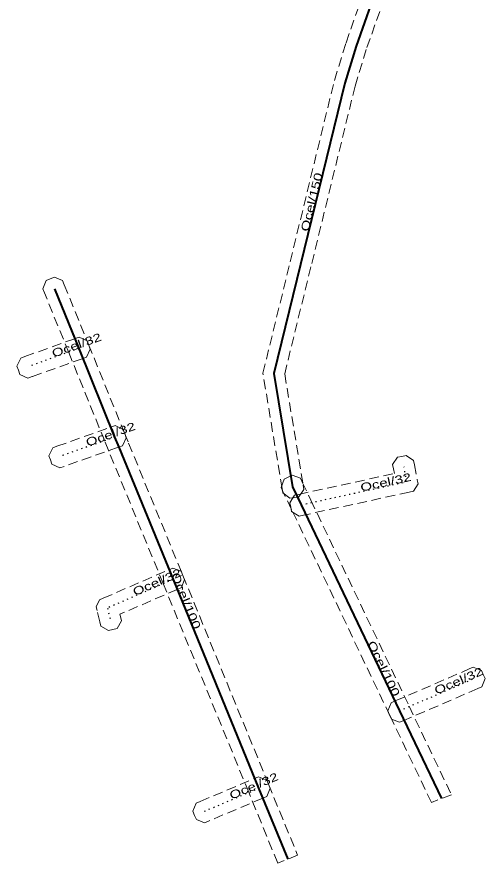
# Model space of a CAD drawing. Extents: x -583333 to -583115, y -1209681 to -1209498.
# Drawn here: x -583253.7 to -583209.9, y -1209656.4 to -1209577.1 of the extents above; entities that cross this region are included whole.
import ezdxf

# ---------------------------------------------------------------- set-up
doc = ezdxf.new("R2010")
doc.units = 0
doc.header["$LTSCALE"] = 0.3
doc.linetypes.add('DOTTED', pattern=[1.5, 0.3, -1.2])
doc.linetypes.add('MEDIUM_DASHED', pattern=[4.5, 3, -1.5])
for name, color, linetype, lineweight in [('1', 7, 'MEDIUM_DASHED', 13), ('14', 7, 'Continuous', 40), ('18', 7, 'DOTTED', 25)]:
    doc.layers.add(name, color=color, linetype=linetype, lineweight=lineweight)
doc.layers.add('20', color=7, linetype='Continuous')

msp = doc.modelspace()

# ---------------------------------------------------------------- linework, layer by layer
at = {"layer": '1'}
for points in [[(-583218.709, -1209573.68), (-583218.846, -1209574.071), (-583220.99, -1209580.183), (-583222.045, -1209583.616), (-583226.179, -1209600.567), (-583228.63, -1209610.589), (-583226.903, -1209621.007), (-583226.835, -1209621.415), (-583227.318, -1209622.089), (-583227.727, -1209622.157), (-583228.135, -1209622.225), (-583228.809, -1209621.742), (-583228.877, -1209621.333), (-583230.67, -1209610.511), (-583228.121, -1209600.093), (-583223.975, -1209583.084), (-583222.89, -1209579.557), (-583220.734, -1209573.409), (-583220.597, -1209573.018), (-583219.85, -1209572.659), (-583219.459, -1209572.796), (-583219.068, -1209572.933)], [(-583227.42, -1209655.685), (-583229.281, -1209656.419), (-583231.995, -1209649.789), (-583240.005, -1209630.239), (-583245.096, -1209617.819), (-583245.476, -1209616.887), (-583248.837, -1209608.596), (-583251.116, -1209602.987), (-583251.272, -1209602.603), (-583250.951, -1209601.84), (-583250.567, -1209601.684), (-583250.183, -1209601.528), (-583249.42, -1209601.849), (-583249.264, -1209602.233), (-583246.983, -1209607.844), (-583243.624, -1209616.133), (-583243.244, -1209617.061), (-583238.155, -1209629.481), (-583230.145, -1209649.031)], [(-583247.183, -1209609.022), (-583247.573, -1209609.162), (-583252.273, -1209610.842), (-583252.663, -1209610.981), (-583253.412, -1209610.627), (-583253.552, -1209610.237), (-583253.691, -1209609.847), (-583253.337, -1209609.098), (-583252.947, -1209608.958), (-583248.247, -1209607.278), (-583247.857, -1209607.139), (-583247.108, -1209607.493), (-583246.968, -1209607.883), (-583246.829, -1209608.273)], [(-583243.825, -1209617.313), (-583244.215, -1209617.452), (-583249.275, -1209619.252), (-583249.665, -1209619.391), (-583250.413, -1209619.035), (-583250.552, -1209618.645), (-583250.691, -1209618.255), (-583250.335, -1209617.507), (-583249.945, -1209617.368), (-583244.885, -1209615.568), (-583244.495, -1209615.429), (-583243.747, -1209615.785), (-583243.608, -1209616.175), (-583243.469, -1209616.565)], [(-583227.708, -1209621.961), (-583227.303, -1209621.873), (-583218.368, -1209619.922), (-583218.452, -1209619.491), (-583218.531, -1209619.084), (-583218.067, -1209618.397), (-583217.661, -1209618.318), (-583217.254, -1209618.239), (-583216.567, -1209618.703), (-583216.488, -1209619.109), (-583216.218, -1209620.499), (-583216.14, -1209620.899), (-583216.589, -1209621.58), (-583216.987, -1209621.667), (-583226.877, -1209623.827), (-583227.282, -1209623.915), (-583227.979, -1209623.468), (-583228.067, -1209623.063), (-583228.155, -1209622.658)], [(-583213.032, -1209650.013), (-583214.897, -1209650.748), (-583218.793, -1209642.58), (-583227.993, -1209623.28), (-583228.793, -1209621.6), (-583228.971, -1209621.226), (-583228.694, -1209620.445), (-583228.32, -1209620.267), (-583227.946, -1209620.089), (-583227.165, -1209620.366), (-583226.987, -1209620.74), (-583226.187, -1209622.42), (-583216.987, -1209641.72)], [(-583238.302, -1209630.613), (-583238.682, -1209630.778), (-583244.046, -1209633.101), (-583243.989, -1209633.33), (-583243.89, -1209633.732), (-583244.318, -1209634.441), (-583244.72, -1209634.541), (-583245.122, -1209634.64), (-583245.831, -1209634.212), (-583245.931, -1209633.81), (-583246.191, -1209632.76), (-583246.279, -1209632.405), (-583245.954, -1209631.748), (-583245.618, -1209631.602), (-583239.478, -1209628.942), (-583239.098, -1209628.778), (-583238.327, -1209629.082), (-583238.162, -1209629.462), (-583237.998, -1209629.842)], [(-583218.667, -1209641.397), (-583218.287, -1209641.232), (-583211.357, -1209638.232), (-583210.977, -1209638.068), (-583210.207, -1209638.373), (-583210.042, -1209638.753), (-583209.878, -1209639.133), (-583210.183, -1209639.903), (-583210.563, -1209640.068), (-583217.493, -1209643.068), (-583217.873, -1209643.232), (-583218.643, -1209642.927), (-583218.808, -1209642.547), (-583218.972, -1209642.167)], [(-583236.911, -1209650.801), (-583236.53, -1209650.639), (-583231.46, -1209648.489), (-583231.079, -1209648.327), (-583230.311, -1209648.639), (-583230.149, -1209649.02), (-583229.987, -1209649.401), (-583230.299, -1209650.169), (-583230.68, -1209650.331), (-583235.75, -1209652.481), (-583236.131, -1209652.643), (-583236.899, -1209652.331), (-583237.061, -1209651.95), (-583237.223, -1209651.569)]]:
    msp.add_lwpolyline(points, close=True, dxfattribs=at)
at = {"layer": '14'}
for points in [[(-583219.79, -1209573.74), (-583221.94, -1209579.87), (-583223.01, -1209583.35), (-583227.15, -1209600.33), (-583229.65, -1209610.55), (-583227.89, -1209621.17)], [(-583250.19, -1209602.61), (-583247.91, -1209608.22), (-583244.55, -1209616.51), (-583244.17, -1209617.44), (-583239.08, -1209629.86), (-583231.07, -1209649.41), (-583228.351, -1209656.052)], [(-583227.89, -1209621.17), (-583227.09, -1209622.85), (-583217.89, -1209642.15), (-583213.965, -1209650.381)]]:
    msp.add_lwpolyline(points, dxfattribs=at)
at = {"layer": '18'}
for p, q in [((-583247.91, -1209608.22), (-583252.61, -1209609.9)), ((-583244.55, -1209616.51), (-583249.61, -1209618.31)), ((-583217.89, -1209642.15), (-583210.96, -1209639.15)), ((-583236.14, -1209651.56), (-583231.07, -1209649.41))]:
    msp.add_line(p, q, dxfattribs=at)
for points in [[(-583227.09, -1209622.85), (-583217.2, -1209620.69), (-583217.47, -1209619.3)], [(-583239.08, -1209629.86), (-583245.22, -1209632.52), (-583244.96, -1209633.57)]]:
    msp.add_lwpolyline(points, dxfattribs=at)

# ---------------------------------------------------------------- texts
at = {"layer": '20', "width": 1.4}
for s, rotation, p in [('Ocel/150', 76.298, (-583226.413, -1209597.304)), ('Ocel/32', 19.669, (-583250.26, -1209609.06)), ('Ocel/32', 19.582, (-583247.08, -1209617.41)), ('Ocel/32', 12.32, (-583221.454, -1209621.619)), ('Ocel/32', 23.423, (-583242.646, -1209631.405)), ('Ocel/100', 292.285, (-583239.274, -1209629.386)), ('Ocel/100', 295.486, (-583220.907, -1209635.821)), ('Ocel/32', 23.408, (-583214.425, -1209640.65)), ('Ocel/32', 22.98, (-583233.605, -1209650.485))]:
    msp.add_text(s, height=0.75, rotation=rotation, dxfattribs=at).set_placement(p)

doc.saveas('drawing.dxf')
